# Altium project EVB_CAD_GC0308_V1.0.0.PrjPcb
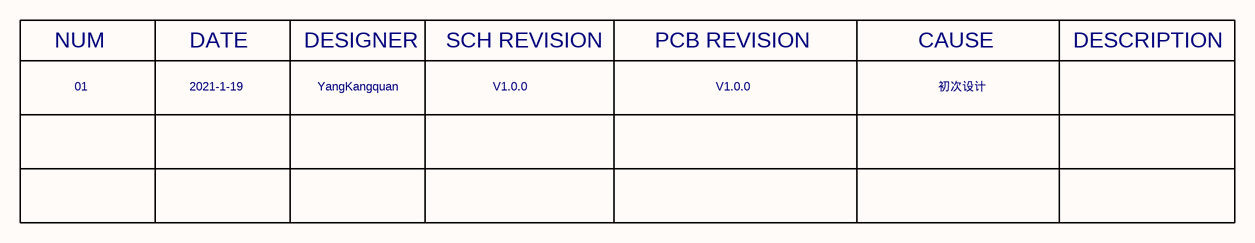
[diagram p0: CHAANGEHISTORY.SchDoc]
4 sheets, 82 parts. Net scope: flat (ports and power ports of the same name join across sheets).
Sheets:
  CHAANGEHISTORY.SchDoc
  BLOCK_DIAGRAM.SchDoc
  SENSOR.SchDoc
  POWER_LED.SchDoc

## Sheet CHAANGEHISTORY.SchDoc: EVB_CAD_GC0308_V1.0.0
size A4; Revision: V1.0.0; SheetNumber: 1; SheetTotal: 4

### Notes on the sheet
- NUM
- 01
- DATE
- 2021-1-19
- DESIGNER
- YangKangquan
- SCH REVISION
- V1.0.0
- PCB REVISION
- CAUSE
- 初次设计
- DESCRIPTION

## Sheet BLOCK_DIAGRAM.SchDoc: EVB_CAD_GC0308_V1.0.0
size A4; Revision: V1.0.0; SheetNumber: 2; SheetTotal: 4
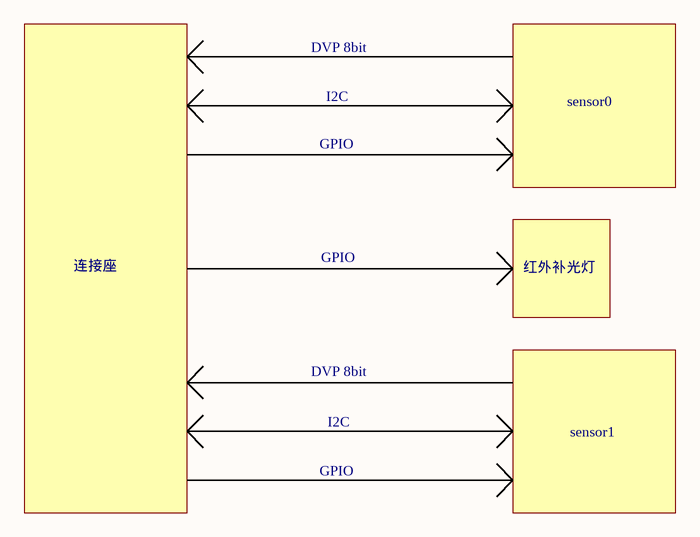
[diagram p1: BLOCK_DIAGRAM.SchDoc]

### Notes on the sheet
- DVP 8bit
- I2C
- sensor0
- GPIO
- 连接座
- 红外补光灯
- sensor1

## Sheet SENSOR.SchDoc: EVB_CAD_GC0308_V1.0.0
size A4; Revision: V1.0.0; SheetNumber: 3; SheetTotal: 4
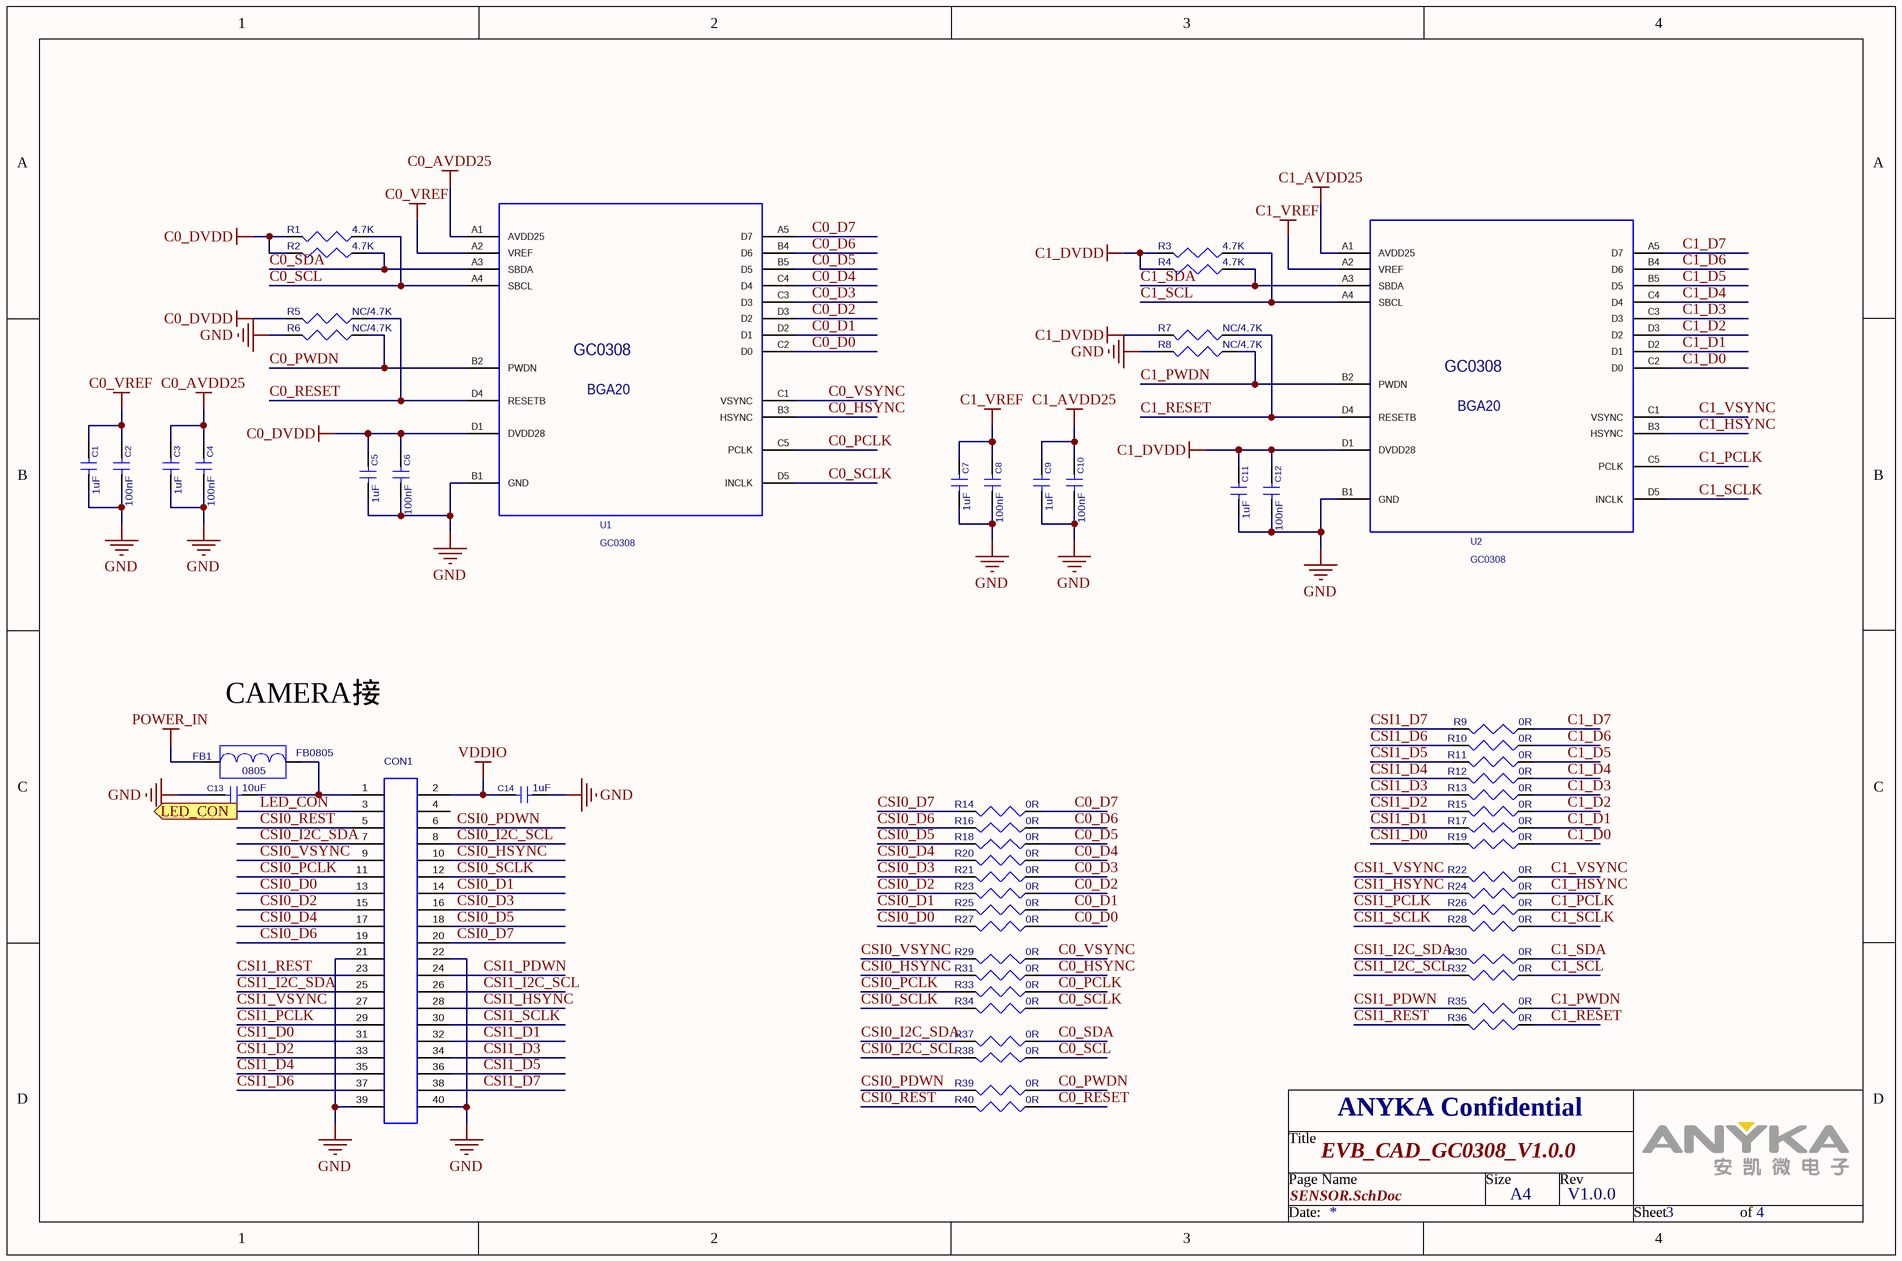
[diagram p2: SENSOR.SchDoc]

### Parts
C1  1uF  [C0603]
C2  100nF  [C0603]
C3  1uF  [C0603]
C4  100nF  [C0603]
C5  1uF  [C0603]
C6  100nF  [C0603]
C7  1uF  [C0603]
C8  100nF  [C0603]
C9  1uF  [C0603]
C10  100nF  [C0603]
C11  1uF  [C0603]
C12  100nF  [C0603]
C13  10uF  [C0603]
C14  1uF  [C0603]
CON1  CON20X2_2MM54  [CON20X2_2MM54]  (value not drawn)
FB1  FB0805  [FB0805]
R1  4.7K  [R0603]
R2  4.7K  [R0603]
R3  4.7K  [R0603]
R4  4.7K  [R0603]
R5  NC/4.7K  [R0603]
R6  NC/4.7K  [R0603]
R7  NC/4.7K  [R0603]
R8  NC/4.7K  [R0603]
R9  0R  [R0603]
R10  0R  [R0603]
R11  0R  [R0603]
R12  0R  [R0603]
R13  0R  [R0603]
R14  0R  [R0603]
R15  0R  [R0603]
R16  0R  [R0603]
R17  0R  [R0603]
R18  0R  [R0603]
R19  0R  [R0603]
R20  0R  [R0603]
R21  0R  [R0603]
R22  0R  [R0603]
R23  0R  [R0603]
R24  0R  [R0603]
R25  0R  [R0603]
R26  0R  [R0603]
R27  0R  [R0603]
R28  0R  [R0603]
R29  0R  [R0603]
R30  0R  [R0603]
R31  0R  [R0603]
R32  0R  [R0603]
R33  0R  [R0603]
R34  0R  [R0603]
R35  0R  [R0603]
R36  0R  [R0603]
R37  0R  [R0603]
R38  0R  [R0603]
R39  0R  [R0603]
R40  0R  [R0603]
U1  GC0308  [BGA20_3MM3X2MM7]
U2  GC0308  [BGA20_3MM3X2MM7]

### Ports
LED_CON (out)

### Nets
C0_AVDD25: C3.1 C4.1 U1.A1(AVDD25)
C0_DVDD: C5.1 C6.1 R1.2 R2.2 R5.2 U1.D1(DVDD28)
C0_VREF: C1.1 C2.1 U1.A2(VREF)
C1_AVDD25: C9.1 C10.1 U2.A1(AVDD25)
C1_DVDD: C11.1 C12.1 R3.2 R4.2 R7.2 U2.D1(DVDD28)
C1_VREF: C7.1 C8.1 U2.A2(VREF)
GND: C1.2 C2.2 C3.2 C4.2 C5.2 C6.2 C7.2 C8.2 C9.2 C10.2 C11.2 C12.2 C13.1 C14.2 CON1.21 CON1.22 CON1.39 CON1.40 R6.2 R8.2 U1.B1(GND) U2.B1(GND)
POWER_IN: FB1.1
VDDIO: C14.1 CON1.2
C0_D0: R27.1 U1.C2(D0)
C0_D1: R25.1 U1.D2(D1)
C0_D2: R23.1 U1.D3(D2)
C0_D3: R21.1 U1.C3(D3)
C0_D4: R20.1 U1.C4(D4)
C0_D5: R18.1 U1.B5(D5)
C0_D6: R16.1 U1.B4(D6)
C0_D7: R14.1 U1.A5(D7)
C0_HSYNC: R31.1 U1.B3(HSYNC)
C0_PCLK: R33.1 U1.C5(PCLK)
C0_PWDN: R6.1 R39.1 U1.B2(PWDN)
C0_RESET: R5.1 R40.1 U1.D4(RESETB)
C0_SCL: R1.1 R38.1 U1.A4(SBCL)
C0_SCLK: R34.1 U1.D5(INCLK)
C0_SDA: R2.1 R37.1 U1.A3(SBDA)
C0_VSYNC: R29.1 U1.C1(VSYNC)
C1_D0: R19.1 U2.C2(D0)
C1_D1: R17.1 U2.D2(D1)
C1_D2: R15.1 U2.D3(D2)
C1_D3: R13.1 U2.C3(D3)
C1_D4: R12.1 U2.C4(D4)
C1_D5: R11.1 U2.B5(D5)
C1_D6: R10.1 U2.B4(D6)
C1_D7: R9.1 U2.A5(D7)
C1_HSYNC: R24.1 U2.B3(HSYNC)
C1_PCLK: R26.1 U2.C5(PCLK)
C1_PWDN: R8.1 R35.1 U2.B2(PWDN)
C1_RESET: R7.1 R36.1 U2.D4(RESETB)
C1_SCL: R3.1 R32.1 U2.A4(SBCL)
C1_SCLK: R28.1 U2.D5(INCLK)
C1_SDA: R4.1 R30.1 U2.A3(SBDA)
C1_VSYNC: R22.1 U2.C1(VSYNC)
CSI0_D0: CON1.13 R27.2
CSI0_D1: CON1.14 R25.2
CSI0_D2: CON1.15 R23.2
CSI0_D3: CON1.16 R21.2
CSI0_D4: CON1.17 R20.2
CSI0_D5: CON1.18 R18.2
CSI0_D6: CON1.19 R16.2
CSI0_D7: CON1.20 R14.2
CSI0_HSYNC: CON1.10 R31.2
CSI0_I2C_SCL: CON1.8 R38.2
CSI0_I2C_SDA: CON1.7 R37.2
CSI0_PCLK: CON1.11 R33.2
CSI0_PDWN: CON1.6 R39.2
CSI0_REST: CON1.5 R40.2
CSI0_SCLK: CON1.12 R34.2
CSI0_VSYNC: CON1.9 R29.2
CSI1_D0: CON1.31 R19.2
CSI1_D1: CON1.32 R17.2
CSI1_D2: CON1.33 R15.2
CSI1_D3: CON1.34 R13.2
CSI1_D4: CON1.35 R12.2
CSI1_D5: CON1.36 R11.2
CSI1_D6: CON1.37 R10.2
CSI1_D7: CON1.38 R9.2
CSI1_HSYNC: CON1.28 R24.2
CSI1_I2C_SCL: CON1.26 R32.2
CSI1_I2C_SDA: CON1.25 R30.2
CSI1_PCLK: CON1.29 R26.2
CSI1_PDWN: CON1.24 R35.2
CSI1_REST: CON1.23 R36.2
CSI1_SCLK: CON1.30 R28.2
CSI1_VSYNC: CON1.27 R22.2
LED_CON: CON1.3 ; port LED_CON
NetC13_2: C13.2 CON1.1 FB1.2

Not connected (* = marked no-connect by the designer): CON1 4

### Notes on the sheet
- (near FB1) CAMERA接口

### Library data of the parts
C1 C3 C5 C7 C9 C11 C14 = CC0301055XX: C/C,1uF,16V,+/-10%,0603; Catalog: 陶瓷电容
C2 C4 C6 C8 C10 C12 = CC0301040XX: C/C,100nF,25V,+/-5%,0603; Catalog: 陶瓷电容
C13 = CC0301060XX: C/C,10uF,25V,+/-5%,0603; Catalog: 陶瓷电容
CON1 = CNHEF4601XX: CON2*20&2X1X3,2.54mm,Female，排母; Catalog: Connector
FB1 = BE0503010XX: BEAD,PZ2012U301-1R5TF,300R,100MHz,0805; Catalog: 贴片磁珠
R1-R4 = CR0304720XX: Res,4.7K,1/10W,+/-5%,0603; Catalog: 贴片电阻
R5-R8 = CR0304720XX: Res,4.7K,1/10W,+/-5%,0603; Remark: NC; Catalog: 贴片电阻
R9-R40 = CR0300000XX: Res,0R,1/10W,+/-5%,0603; Catalog: 贴片电阻
U1 U2 = JCBGACS11XX: CMOS Image Sensor,Galaxycore,GC0308,CSP-20,1/6.5"; Catalog: 集成电路

## Sheet POWER_LED.SchDoc: EVB_CAD_GC0308_V1.0.0
size A4; Revision: V1.0.0; SheetNumber: 4; SheetTotal: 4
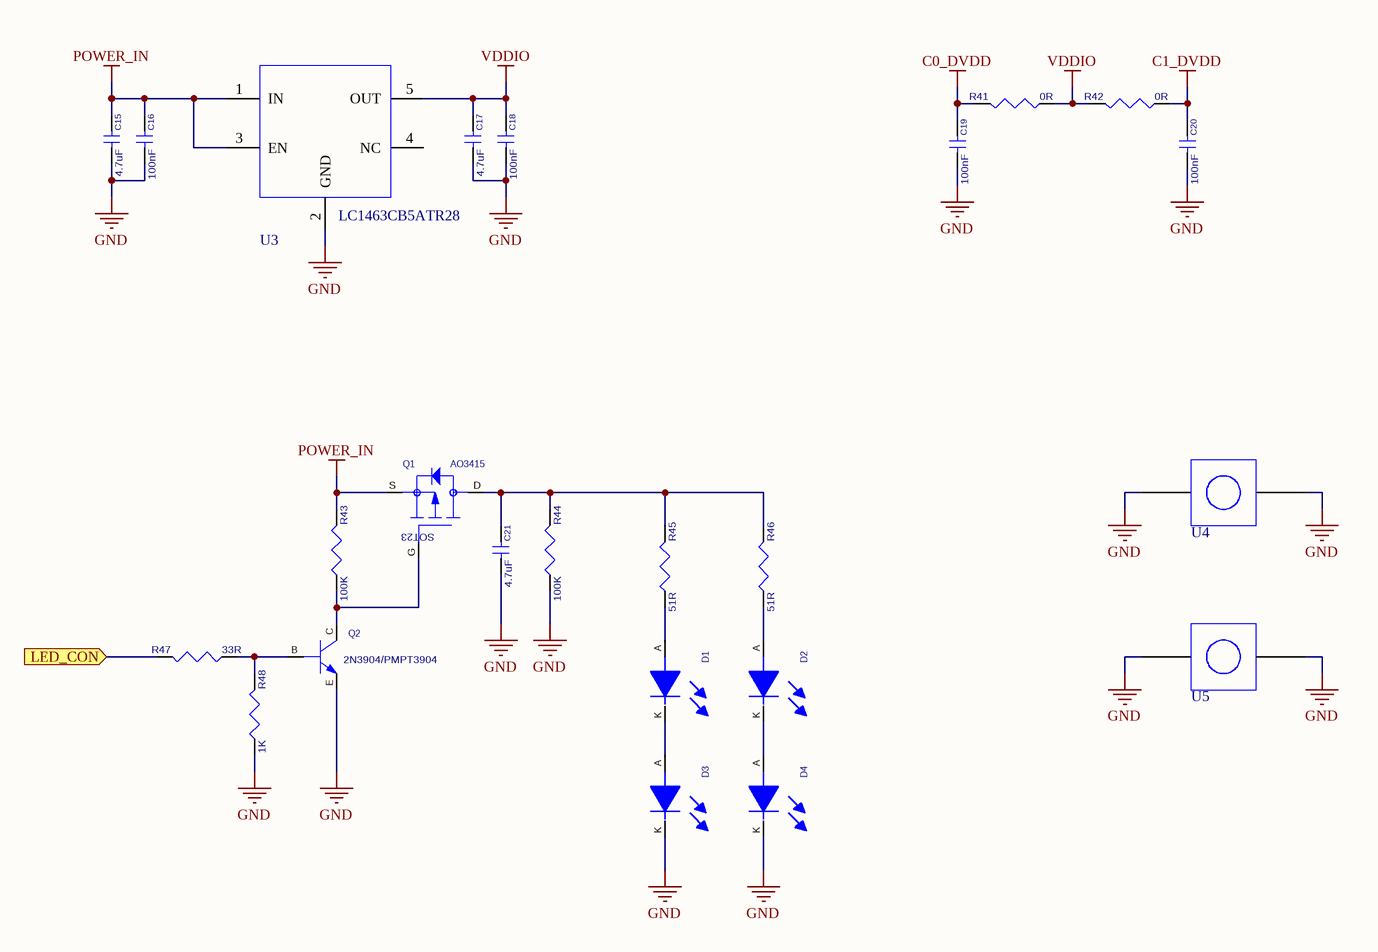
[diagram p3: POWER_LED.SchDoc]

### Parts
C15  4.7uF  [C0603]
C16  100nF  [C0603]
C17  4.7uF  [C0603]
C18  100nF  [C0603]
C19  100nF  [C0603]
C20  100nF  [C0603]
C21  4.7uF  [C0603]
D1  LED_2MM54  [LED_2MM54]  (value not drawn)
D2  LED_2MM54  [LED_2MM54]  (value not drawn)
D3  LED_2MM54  [LED_2MM54]  (value not drawn)
D4  LED_2MM54  [LED_2MM54]  (value not drawn)
Q1  AO3415  [SOT23_GDS]
Q2  value 2N3904/PMPT3904  [2N3904/PMBT3904]  (hidden comment: 2N3904/PMBT3904)
R41  0R  [R0603]
R42  0R  [R0603]
R43  100K  [R0603]
R44  100K  [R0603]
R45  51R  [R0603]
R46  51R  [R0603]
R47  33R  [R0603]
R48  1K  [R0603]
U3  LC1463CB5ATR28  [LC1463CB5ATR18_SOT23-5]
U4  camera  [CAMERA_COVER]  (value not drawn)
U5  camera  [CAMERA_COVER]  (value not drawn)

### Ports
LED_CON (in)

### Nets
C0_DVDD: C19.1 R41.2
C1_DVDD: C20.1 R42.1
GND: C15.2 C16.2 C17.2 C18.2 C19.2 C20.2 C21.2 D3.K D4.K Q2.E R44.1 R48.1 U3.2(GND) U4.?1 U4.?2 U5.?1 U5.?2
POWER_IN: C15.1 C16.1 Q1.S R43.2 U3.1(IN) U3.3(EN)
VDDIO: C17.1 C18.1 R41.1 R42.2 U3.5(OUT)
LED_CON: R47.2 ; port LED_CON
NetC21_1: C21.1 Q1.D R44.2 R45.2 R46.2
NetD1_A: D1.A R45.1
NetD1_K: D1.K D3.A
NetD2_A: D2.A R46.1
NetD2_K: D2.K D4.A
NetQ1_G: Q1.G Q2.C R43.1
NetQ2_B: Q2.B R47.1 R48.2

Not connected (* = marked no-connect by the designer): U3 4(NC)

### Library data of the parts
C15 C17 C21 = CC0304752XX: C/C,4.7uF,10V +/-10%,0603; Catalog: 陶瓷电容
C16 C18-C20 = CC0301040XX: C/C,100nF,25V,+/-5%,0603; Catalog: 陶瓷电容
D1-D4 = LE25RXX05XX: 红外补光灯LED ，850nm,Ф3,间距2MM4， 红外灯60度; Color: ???; Sim.Analog.Prefix: D; Sim.Analog.Order: Model$; Catalog: 二极管
Q1 = MS052SW02XX: AO3415-sot23,E-P-CH,GP; PCB DECAL: AO3413_SOT23_GDS_P; Catalog: MOS
Q2 = TR05NGN00XX: 2N3904/PMBT3904,SOT-23,NPN,GP; PCB DECAL: 2N3904/PMBT3904_SOT23_BCE_NPN; Catalog: 三极管
R41 R42 = CR0300000XX: Res,0R,1/10W,+/-5%,0603; Catalog: 贴片电阻
R43 R44 = CR0310030XX: Res,100K,1/10W,+/-1%,0603; Catalog: 贴片电阻
R45 R46 = CR0351R00XX: Res,51R,1/10W,+/-1%,0603; Catalog: 贴片电阻
R47 = CR0333R00XX: Res,33R,1/10W,+/-1%,0603; Catalog: 贴片电阻
R48 = CR0301020XX: Res,1K,1/10W,+/-5%,0603; Catalog: 贴片电阻
U3 = JCSXTPW74XX: 非通用 PowerIC,Leadchip,LC1463CB5ATR28,SOT,5pin; Catalog: 集成电路
U4 U5 = 11111111113: Catalog: 镜头

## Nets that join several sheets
C0_DVDD: SENSOR (6 pins), POWER_LED (C19.1 R41.2)
C1_DVDD: SENSOR (6 pins), POWER_LED (C20.1 R42.1)
GND: SENSOR (22 pins), POWER_LED (17 pins)
POWER_IN: SENSOR (FB1.1), POWER_LED (6 pins)
VDDIO: SENSOR (C14.1 CON1.2), POWER_LED (5 pins)
LED_CON: SENSOR (CON1.3), POWER_LED (R47.2)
